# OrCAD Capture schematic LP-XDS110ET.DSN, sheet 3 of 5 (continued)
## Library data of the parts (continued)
U33 U38 = IC_SWITCH_TS3A24159_SON10: IC, ANALOG, 0.3R DUAL SPDT ANALOG SWITCH DUAL-CHANNEL 2:1 MULTIPLEXER/DEMULTIPLEXER, 1.65V TO 3.6V, SON10-EP, SMD; ALT_SYMBOLS: SON50P300X300X100-11A2L,SON50P300X300X100-11A2M; Additional Datasheet URL: http://www.ti.com/litv/pdf/mpds117k; AutoDoc File: https://notefied-dynamic-precision.com/DB/Apps/Desktop/Item/Object.aspx?id=99151; BU Name: DYNAMIC PRECISION GDANSK; Budget Currency: USD; Budget Price: 0.35; Budgetary Price: 0.35 USD; Client Status: UNDER_REVIEW; Country of Origin: Malaysia; Datasheet URL: http://www.ti.com/lit/ds/symlink/ts3a24159.pdf; Datasheet URL 1: http://www.ti.com/lit/ds/symlink/ts3a24159.pdf; Datasheet URL 2: http://www.ti.com/litv/pdf/mpds117k; Lead Time: 2; Mass: 0.0248g; Max Oper Temp: +85DEGC; Maximum Operating Temperature: +85DEGC; Min Oper Temp: -40DEGC; Minimum Operating Temperature: -40DEGC; Mounting Type: SMD; NOTEfied URL: https://notefied-dynamic-precision.com/NOTEfiedWebInterface/part/show?partNumber=18-30805; PCB Package: SON10-EP; Packing Size: 3000; Packing Type: Tape & Reel; Part Number: 18-30805; Part Type: IC|ANALOG|SWITCH; REACH/SVHC Compliance: Compliant; REACH/SVHC Details: SVHC List Version Jan 12, 2017; REACH/SVHC Source: REACH Declaration; REACH/SVHC Status: Unaffected; ROHS: Compliant; Rated Voltage: 1.65V TO 3.6V; Revision: R008; RoHS Status: ROHS_COMPLIANT; Rtd Voltage: 1.65V TO 3.6V; Status: Released; Texas Part Status: Under Review; Type: IC; Vendor: TEXAS INSTRUMENTS; Vendor Part Number: TS3A24159DRCR; Vendor Part Status: Active; Weight: 0.0248g
U34 = IC_LOGIC_SN74LVC2G74_VSSOP8: IC, DIGITAL, LOGIC, D-TYPE FLIP-FLOP WITH CLEAR AND PRESET, 1.65V TO 5.5V, VSSOP8, SMD; ALT_SYMBOLS: SOP50P310X90-8L,SOP50P310X90-8M; Additional Datasheet URL: http://www.ti.com/litv/pdf/mpds050d; AutoDoc File: https://notefied-dynamic-precision.com/DB/Apps/Desktop/Item/Object.aspx?id=83835; BU Name: DYNAMIC PRECISION GDANSK; Budget Currency: USD; Budget Price: 0.20; Budgetary Price: 0.2 USD; CLASS: IC; Client Status: UNDER_REVIEW; Country of Origin: Thailand; Datasheet URL: http://www.ti.com/lit/ds/symlink/sn74lvc2g74.pdf; Datasheet URL 1: http://www.ti.com/lit/ds/symlink/sn74lvc2g74.pdf; Datasheet URL 2: http://www.ti.com/litv/pdf/mpds050d; Lead Time: 6; Mass: 0.011g; Max Oper Temp: +85DEGC; Maximum Operating Temperature: +85DEGC; Min Oper Temp: -40DEGC; Minimum Operating Temperature: -40DEGC; Mounting Type: SMD; NOTEfied URL: https://notefied-dynamic-precision.com/NOTEfiedWebInterface/part/show?partNumber=18-27150; PCB Package: VSSOP8; Packing Size: 3000; Packing Type: Tape & Reel; Part Number: 18-27150; Part Type: IC|DIGITAL|LOGIC|FLIP FLOP; ROHS: Compliant; Rated Voltage: 1.65V TO 5.5V; Revision: R005; RoHS Status: ROHS_COMPLIANT; Rtd Voltage: 1.65V TO 5.5V; Status: Released; Type: IC; Vendor: TEXAS INSTRUMENTS; Vendor Part Number: SN74LVC2G74DCUR; Vendor Part Status: Active; Weight: 0.011g
U35 = IC_ADC_ADS127L01_QFP32_0: IC, MIXED, 24-BIT WIDE-BANDWIDTH ANALOG TO DIGITAL CONVERTER, 2.7V TO 3.6V/1.7V TO 3.6V, TQFP32, SMD; ALT_SYMBOLS: QFP50P700X700X120-32A2L,QFP50P700X700X120-32A2M; Additional Datasheet URL: http://www.ti.com/litv/pdf/mpqf027a; AutoDoc File: https://notefied-dynamic-precision.com/DB/Apps/Desktop/Item/Object.aspx?id=115279; BU Name: DYNAMIC PRECISION GDANSK; Budget Currency: USD; Budget Price: 8.34; Budgetary Price: 8.34 USD; Client Status: UNDER_REVIEW; Datasheet URL: http://www.ti.com/lit/ds/symlink/ads127l01.pdf; Datasheet URL 1: http://www.ti.com/lit/ds/symlink/ads127l01.pdf; Max Oper Temp: +125DEGC; Maximum Operating Temperature: +125DEGC; Min Oper Temp: -40DEGC; Minimum Operating Temperature: -40DEGC; Mounting Type: SMD; NOTEfied URL: https://notefied-dynamic-precision.com/NOTEfiedWebInterface/part/show?partNumber=18-33431; PCB Package: TQFP32; Packing Size: 250; Packing Type: Tube; Part Number: 18-33431; Part Type: IC|MIXED|ADC; REACH/SVHC Compliance: Compliant; REACH/SVHC Details: SVHC List Version Jan 12, 2017; REACH/SVHC Source: REACH Declaration; REACH/SVHC Status: Unaffected; ROHS: Compliant; Rated Voltage: 2.7V TO 3.6V/1.7V TO 3.6V; Revision: R007; RoHS Status: ROHS_COMPLIANT; Rtd Voltage: 2.7V TO 3.6V/1.7V TO 3.6V; Status: Released; Texas Part Status: Under Review; Type: IC; Vendor: TEXAS INSTRUMENTS; Vendor Part Status: Active
U36 = IC_OPAMP_INA118U_SO8: IC, ANALOG, INSTRUMENTATION AMPLIFIER, -/+15V, SO8, SMD; ALT_SYMBOLS: SOIC127P600X175-8A2L,SOIC127P600X175-8A2M; Additional Datasheet URL: http://www.ti.com/litv/pdf/msoi002j; Budgetary Price: 10.16 USD; CLASS: IC; Datasheet URL: http://www.ti.com/lit/ds/symlink/ina118.pdf; Mass: 0.085g; Maximum Operating Temperature: +125DEGC; Minimum Operating Temperature: -40DEGC; Mounting Type: SMD; NOTEfied URL: https://notefied-dynamic-precision.com/NOTEfiedWebInterface/part/show?partNumber=18-34413; PCB Package: SO8; Packing Size: 75; Packing Type: Tube; Part Number: 18-34413; Part Type: IC|ANALOG|AMPLIFIER; REACH/SVHC Compliance: Compliant; REACH/SVHC Details: SVHC List Version Jul 07, 2017; REACH/SVHC Source: REACH Declaration; REACH/SVHC Status: Unaffected; ROHS: Compliant; Rated Voltage: -/+15V; Revision: R001; Status: Released; Texas Part Status: Under Review; Type: IC; Vendor: TEXAS INSTRUMENTS; Vendor Part Status: Active
U37 = IC_OPAMP_THS4551_QFN10: IC, ANALOG, LOW NOISE, PRECISION, 150MHz, FULLY DIFFERENTIAL AMPLIFIER, 2.7V TO 5.4V, QFN10-EP, SMD; ALT_SYMBOLS: QFNFCP50P200X200X80-10A2L,QFNFCP50P200X200X80-10A2M; Additional Datasheet URL: http://www.ti.com/lit/ml/mpqf225a/mpqf225a.pdf; Budgetary Price: 1.39 USD; Datasheet URL: http://www.ti.com/lit/ds/symlink/ths4551.pdf; Frequency: 150MHz; Mass: 0.0116g; Maximum Operating Temperature: +125DEGC; Minimum Operating Temperature: -40DEGC; Mounting Type: SMD; NOTEfied URL: https://notefied-dynamic-precision.com/NOTEfiedWebInterface/part/show?partNumber=18-34391; PCB Package: QFN10-EP; Packing Size: 3000; Packing Type: Tape & Reel; Part Number: 18-34391; Part Type: IC|ANALOG|AMPLIFIER; REACH/SVHC Compliance: Compliant; REACH/SVHC Details: SVHC List Version Jul 07, 2017; REACH/SVHC Source: REACH Declaration; REACH/SVHC Status: Unaffected; ROHS: Compliant; Rated Voltage: 2.7V TO 5.4V; Revision: R001; Status: Released; Texas Part Status: Under Review; Type: IC; Vendor: TEXAS INSTRUMENTS; Vendor Part Number: THS4551IRUNR; Vendor Part Status: Active
U39 = IC_SWITCH_TS3A4751_QFN14: IC, ANALOG, 0.9R LOW-VOLTAGE SINGLE-SUPPLY QUAD SPST ANALOG SWITCH, 1.6V TO 3.6V, QFN14, SMD; ALT_SYMBOLS: QFNFC40P200X200X40-14A2L,QFNFC40P200X200X40-14A2M; Additional Datasheet URL: http://www.ti.com/litv/pdf/mpqf212b; AutoDoc File: https://notefied-dynamic-precision.com/DB/Apps/Desktop/Item/Object.aspx?id=99155; BU Name: DYNAMIC PRECISION GDANSK; Budget Currency: USD; Budget Price: 0.42; Budgetary Price: 0.42 USD; Client Status: UNDER_REVIEW; Country of Origin: United States; Datasheet URL: http://www.ti.com/lit/ds/symlink/ts3a4751.pdf; Datasheet URL 1: http://www.ti.com/lit/ds/symlink/ts3a4751.pdf; Datasheet URL 2: http://www.ti.com/litv/pdf/mpqf212b; Lead Time: 4; Mass: 0.0038g; Max Oper Temp: +85DEGC; Maximum Operating Temperature: +85DEGC; Min Oper Temp: -40DEGC; Minimum Operating Temperature: -40DEGC; Mounting Type: SMD; NOTEfied URL: https://notefied-dynamic-precision.com/NOTEfiedWebInterface/part/show?partNumber=18-30809; PCB Package: QFN14; Packing Size: 3000; Packing Type: Tape & Reel; Part Number: 18-30809; Part Type: IC|ANALOG|SWITCH; REACH/SVHC Compliance: Compliant; REACH/SVHC Details: SVHC List Version Jan 12, 2017; REACH/SVHC Source: REACH Declaration; REACH/SVHC Status: Unaffected; ROHS: Compliant; Rated Voltage: 1.6V TO 3.6V; Revision: R008; RoHS Status: ROHS_COMPLIANT; Rtd Voltage: 1.6V TO 3.6V; Status: Released; Texas Part Status: Under Review; Type: IC; Vendor: TEXAS INSTRUMENTS; Vendor Part Status: Active; Weight: 0.0038g
U40 = IC_REF_REF6025_VSSOP8: IC, ANALOG, HIGH PRECISION VOLTAGE REFERENCE, VIN:3V TO 5.5V, VOUT:2.5V, VSSOP8, SMD; ALT_SYMBOLS: SOP65P490X110-8A2L,SOP65P490X110-8A2M; Additional Datasheet URL: http://www.ti.com/lit/ml/mpds028d/mpds028d.pdf; Budgetary Price: 3 USD; Datasheet URL: http://www.ti.com/lit/ds/symlink/ref6025.pdf; Mass: 0.0252g; Maximum Operating Temperature: +125DEGC; Minimum Operating Temperature: -40DEGC; Mounting Type: SMD; NOTEfied URL: https://notefied-dynamic-precision.com/NOTEfiedWebInterface/part/show?partNumber=18-34390; PCB Package: VSSOP8; Packing Size: 2500; Packing Type: Tape & Reel; Part Number: 18-34390; Part Type: IC|ANALOG|PM|REFERENCE; REACH/SVHC Compliance: Compliant; REACH/SVHC Details: SVHC List Version Jul 07, 2017; REACH/SVHC Source: REACH Declaration; REACH/SVHC Status: Unaffected; ROHS: Compliant; Rated Voltage: 2.5V; Revision: R001; Status: Released; Texas Part Status: Under Review; Type: IC; Vendor: TEXAS INSTRUMENTS; Vendor Part Number: REF6025IDGKR; Vendor Part Status: Active
U41 = IC_OPAMP_OPA320_SOT23-5: IC, ANALOG, RAIL-TO-RAIL I/O CMOS OPERATIONAL AMPLIFIER, -/+0.9V TO 5.5V, SOT23-5, SMD; ALT_SYMBOLS: SOT95P280X145-5A2L,SOT95P280X145-5A2M; Additional Datasheet URL: http://www.ti.com/litv/pdf/mpds018l; AutoDoc File: https://notefied-dynamic-precision.com/DB/Apps/Desktop/Item/Object.aspx?id=113801; BU Name: DYNAMIC PRECISION GDANSK; Budget Currency: USD; Budget Price: 0.95; Budgetary Price: 0.95 USD; Client Status: UNDER_REVIEW; Country of Origin: Thailand; Datasheet URL: http://www.ti.com/lit/ds/symlink/opa320.pdf; Datasheet URL 1: http://www.ti.com/lit/ds/symlink/opa320.pdf; Datasheet URL 2: http://www.ti.com/lit/ml/mpds018l/mpds018l.pdf; Lead Time: 6; Mass: 0.0203g; Max Oper Temp: +125DEGC; Maximum Operating Temperature: +125DEGC; Min Oper Temp: -40DEGC; Minimum Operating Temperature: -40DEGC; Mounting Type: SMD; NOTEfied URL: https://notefied-dynamic-precision.com/NOTEfiedWebInterface/part/show?partNumber=18-32984; PCB Package: SOT23-5; Packing Size: 250; Packing Type: Tape & Reel; Part Number: 18-32984; Part Type: IC|ANALOG|AMPLIFIER; ROHS: Compliant; Rated Voltage: -/+0.9V TO 5.5V; Revision: R007; RoHS Status: ROHS_COMPLIANT; Rtd Voltage: -/+0.9V TO 5.5V; Status: Released; Type: IC; Vendor: TEXAS INSTRUMENTS; Vendor Part Number: OPA320AIDBVT; Vendor Part Status: Active; Weight: 0.0203g
Y5 = XTAL_GEN_EN_V1: CRYSTAL, OSCILLATOR, XO, 16.384MHz, -50PPM/+50PPM, 3.3V, -20DEGC/+70DEGC, SMD; ALT_SYMBOLS: OSCSC254P320X500X130-4A2L,OSCSC254P320X500X130-4A2M; Additional Datasheet URL: N/A; Datasheet URL: https://www.ctscorp.com/wp-content/uploads/636.pdf; Maximum Operating Temperature: +70DEGC; Maximum Stability: +50PPM; Minimum Operating Temperature: -20DEGC; Minimum Stability: -50PPM; Mounting Type: SMD; NOTEfied URL: https://notefied-dynamic-precision.com/NOTEfiedWebInterface/part/show?partNumber=12-01320; Packing Size: 1000; Packing Type: Tape & Reel; Part Number: 12-01320; Part Type: Crystal|OSCILLATOR|XO; REACH/SVHC Compliance: Compliant; REACH/SVHC Details: SVHC List Version Jul 07, 2017; REACH/SVHC Source: Material Declaration; REACH/SVHC Status: Unaffected; ROHS: Compliant; Rated Voltage: 3.3V; Revision: R002; Status: Released; Texas Part Status: Under Review; Type: Crystal; Vendor: CTS COMPONENTS; Vendor Part Number: 636L3C016M38400; Vendor Part Status: Active

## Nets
GND: C114.2 C115.2 C116.2 C117.2 C118.2 C119.2 C120.2 C121.2 C122.2 C124.1 C125.1 C126.1 C127.2 C128.2 C133.2 C134.2 C136.2 C137.2 C138.2 C139.2 C140.2 C141.2 C142.2 C143.2 C144.2 C145.2 C147.2 C149.2 R97.2 R105.1 R116.1 R117.1 R118.1 R122.1 R123.1 R125.1 R126.2 R127.2 R128.2 R129.2 R130.2 R136.1 U33.6(GND) U33.11(EGP) U34.4(GND) U35.5(AGND) U35.10(REFN) U35.13(FILTER0) U35.14(FSMODE) U35.18(DAISYIN) U35.26(DGND) U35.30(FORMAT) U35.31(AGND) U36.4(V-) U37.5(VS-) U38.6(GND) U38.7(NC2) U38.8(IN2) U38.9(COM2) U38.10(NO2) U38.11(EGP) U39.7(GND) U39.10(COM4) U39.11(NO4) U39.12(IN4) U40.7(GND_F) U40.8(GND_S) U41.2(V-) Y5.2(GND) ; also on sheet 1 2 4 5
ET_1V8: C128.1 U35.1(LVDD) ; also on sheet 4
ET_3V3: C126.2 C141.1 C142.1 L333.1 L334.2 U37.3(nPD) U37.10(VS+) U40.1(VIN) U40.2(EN) U41.5(V+) ; also on sheet 4
ET_5V0: C125.2 U36.7(V+) ; also on sheet 4
ET_AVDD: C119.1 C120.1 C121.1 C122.1 L334.1 R98.1 U35.6(AVDD) U35.32(AVDD)
ET_BYPASS: U33.4(IN1) U33.8(IN2) ; also on sheet 2
ET_CAL0: R129.1 U39.13(IN1) ; also on sheet 2
ET_CAL1: R128.1 U39.5(IN2) ; also on sheet 2
ET_CAL2: R127.1 U39.6(IN3) ; also on sheet 2
ET_CALIBRATE: U38.4(IN1) ; also on sheet 2
ET_DVDD: C116.1 C117.1 L332.1 L333.2 R96.1 R114.1 R119.1 U35.27(DVDD) Y5.1(EOH)
ET_PM2: R96.2 U35.17(START) ; also on sheet 2
ET_PN3: R114.2 U35.28(nRESET/nPWDN) ; also on sheet 2
ET_SSICLK: U35.22(SCLK) ; also on sheet 2
ET_SSIDAT0: U35.21(DIN) ; also on sheet 2
ET_SSIDAT1: U35.20(DOUT) ; also on sheet 2
ET_SSIFSS: U35.19(nDRDY/FSYNC) ; also on sheet 2
ET_VREF: C127.1 C146.1 R121.1 U35.9(REFP) U40.5(OUT_S) U40.6(OUT_F)
LP_VDD: U38.5(NC1) ; also on sheet 1
LS_VDD: U33.3(COM1) U33.9(COM2) ; also on sheet 1
SW_VDD: C114.1 C139.1 C140.1 U33.1(VCC) U38.1(VCC) U39.14(VCC) ; also on sheet 4
VCM: R100.1 R109.2 R111.2 R131.1 U41.1(OUT)
N2986125: C115.1 C118.1 L332.2 U34.6(nCLR) U34.7(nPRE) U34.8(VCC) Y5.4(VCC)
N2986433: R99.2 R107.2 U33.2(NO1)
N2986453: U34.1(CLK) Y5.3(OUT)
N2986493: U34.2(D) U34.3(nQ)
N2986501: R94.2 U34.5(Q)
N2986505: R94.1 U35.24(CLK)
N2986529: R107.1 R108.2 U33.7(NC2) U38.3(COM1)
N2986711: C129.1 R95.2 R101.1 R102.2
N2986719: R95.1 R103.1 R104.2
N2986959: C123.1 C130.1 R102.1 U37.4(VIN+)
N2986967: C123.2 R103.2 U37.1(OUT-)
N2987171: R97.1 U35.29(HR)
N2987283: C124.2 C132.1 R99.1 U36.3(+IN)
N2987343: R98.2 U35.8(nINTLDO)
N2987399: R137.2 U36.1(RG1)
N2987403: R137.1 U36.8(RG2)
N2987531: R101.2 U36.6(OUT)
N2987583: C131.1 R104.1 U35.3(AINN)
N2987595: R105.2 U35.23(nCS)
N2987655: C132.2 C134.1 R108.1 U36.2(-IN)
N2987667: C133.1 R111.1 U37.7(VOCM)
N2987683: C131.2 R113.1 U35.4(AINP)
N2987711: R100.2 U36.5(REF)
N2987751: C130.2 C135.1 R110.1 U37.6(VIN-)
N2987759: C135.2 R112.2 U37.9(OUT+)
N2987811: C136.1 U35.2(CAP1)
N2987883: C129.2 R109.1 R110.2 R120.2
N2987963: C137.1 U35.11(CAP2)
N2988091: R112.1 R113.2 R120.1
N2988111: C138.1 U35.25(CAP3)
N2988211: R116.2 U35.7(REXT)
N2988383: R117.2 U35.16(OSR0)
N2988415: R118.2 U35.15(OSR1)
N2988503: R119.2 U35.12(FILTER1)
N2988673: U38.2(NO1) U39.2(COM1) U39.4(COM2) U39.9(COM3)
N2989115: C143.1 R123.2 U39.1(NO1)
N2989191: R136.2 U40.3(SS)
N2989203: C147.1 R121.2 R126.1 U41.3(IN+)
N2989279: C145.1 U40.4(FILT)
N2989287: C146.2 R122.2
N2989331: C144.1 R125.2 U39.3(NO2)
N2989451: R131.2 U41.4(IN-)
N2989545: C149.1 R130.1 U39.8(NO3)

Not connected (* = marked no-connect by the designer): U33 5(NC1)* 10(NO2)*; U37 2(NC)* 8(NC)*

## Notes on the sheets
sheet 3
- EnergyTrace
- LOW
- LOW
- HIGH
- LOW
- LOW
- LOW
- HIGH
- Calibration
- 40.2 mA
- 90.4 mA
- 1.5mA
